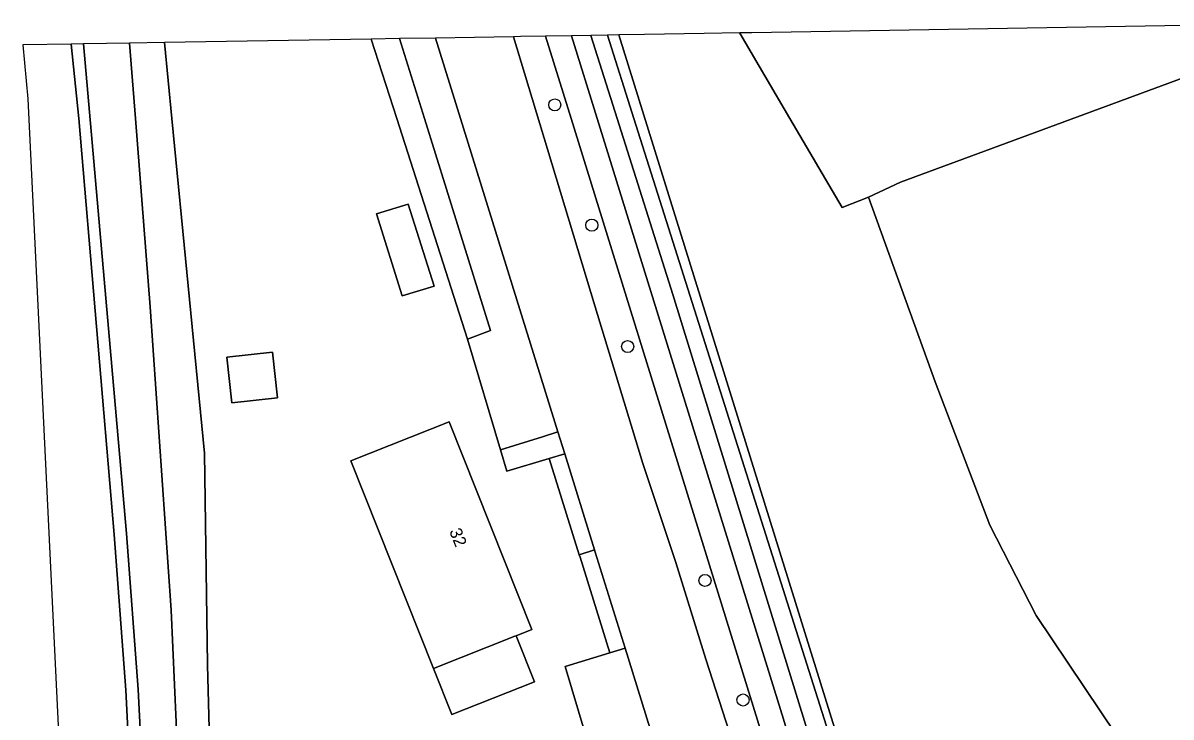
# Model space of a CAD drawing. Extents: x 162510 to 163918, y 388494 to 389774.
# Drawn here: x 162581.4 to 162674.3, y 389701.6 to 389757.7 of the extents above; entities that cross this region are included whole.
import ezdxf

# ---------------------------------------------------------------- set-up
doc = ezdxf.new("R2010")
doc.units = 0
for name, color, linetype in [('IMGEO_Berm_groen', 7, 'Continuous'), ('IMGEO_Boom', 7, 'Continuous'), ('IMGEO_Erf', 7, 'Continuous'), ('IMGEO_Fietspad_gesloten', 7, 'Continuous'), ('IMGEO_Grasland_agrarisch', 7, 'Continuous'), ('IMGEO_Groenvoorziening', 7, 'Continuous'), ('IMGEO_Pand', 7, 'Continuous'), ('IMGEO_Pand_nummerreeks', 7, 'Continuous'), ('IMGEO_Rijbaan_lokaal_gesloten', 7, 'Continuous'), ('IMGEO_Rijbaan_lokaal_open', 7, 'Continuous'), ('IMGEO_Rijbaan_regionaal_gesloten', 7, 'Continuous'), ('IMGEO_Voetpad_halfverhard', 7, 'Continuous'), ('IMGEO_Waterloop', 7, 'Continuous')]:
    doc.layers.add(name, color=color, linetype=linetype)

msp = doc.modelspace()

# ---------------------------------------------------------------- linework, layer by layer
at = {"layer": 'IMGEO_Berm_groen'}
for points in [[(162657.306, 389644.486), (162657.276, 389644.598), (162654.694, 389654.432), (162647.267, 389680.414), (162625.711, 389750), (162623.648, 389756.662), (162621.623, 389756.628), (162621.069, 389756.619)], [(162621.069, 389756.619), (162623.811, 389747.513), (162627.663, 389734.752), (162631.516, 389722.082), (162634.181, 389714.087), (162636.629, 389706.24), (162641.701, 389690.442), (162643.356, 389684.664)]]:
    msp.add_lwpolyline(points, dxfattribs=at)
at = {"layer": 'IMGEO_Boom'}
for centre in [(162624.392, 389751.1), (162627.393, 389741.373), (162630.292, 389731.545), (162636.548, 389712.625), (162639.625, 389702.949)]:
    msp.add_circle(centre, 0.489, dxfattribs=at)
at = {"layer": 'IMGEO_Erf'}
for points in [[(162687.277, 389757.733), (162683.292, 389757.666), (162640.344, 389756.943), (162639.372, 389756.927), (162639.379, 389756.914), (162643.424, 389750), (162647.635, 389742.802), (162649.788, 389743.642), (162652.361, 389744.846)], [(162609.981, 389742.277), (162612.545, 389743.081), (162614.626, 389736.448), (162612.061, 389735.643)], [(162598.275, 389726.987), (162597.869, 389730.701), (162601.554, 389731.103), (162601.959, 389727.389)], [(162607.907, 389722.307), (162615.852, 389725.465), (162622.536, 389708.654), (162621.265, 389708.149), (162622.743, 389704.431), (162616.069, 389701.778), (162614.591, 389705.496)]]:
    msp.add_lwpolyline(points, close=True, dxfattribs=at)
for points in [[(162627.859, 389696.902), (162625.249, 389705.649), (162628.847, 389706.767), (162626.436, 389714.516), (162626.377, 389714.707), (162623.952, 389722.498), (162620.528, 389721.472), (162620.012, 389723.199), (162617.339, 389732.159), (162611.612, 389750), (162609.55, 389756.425), (162592.82, 389756.143)], [(162592.82, 389756.143), (162593.42, 389750), (162596.065, 389722.909), (162596.294, 389705.791), (162596.643, 389692.431)]]:
    msp.add_lwpolyline(points, dxfattribs=at)
at = {"layer": 'IMGEO_Fietspad_gesloten'}
for points in [[(162656.158, 389656.625), (162642.905, 389701.409), (162627.834, 389750), (162625.756, 389756.697), (162623.648, 389756.662)], [(162623.648, 389756.662), (162625.711, 389750), (162647.267, 389680.414), (162654.694, 389654.432), (162657.276, 389644.598), (162657.306, 389644.486)]]:
    msp.add_lwpolyline(points, dxfattribs=at)
at = {"layer": 'IMGEO_Grasland_agrarisch'}
msp.add_lwpolyline([(162687.277, 389757.733), (162652.361, 389744.846), (162649.788, 389743.642), (162655.173, 389728.688), (162659.589, 389717.108), (162663.344, 389709.783), (162669.846, 389700.093), (162669.917, 389688.356), (162669.136, 389680.314), (162662.579, 389669.049), (162659.003, 389663.387), (162661.443, 389654.652), (162662.113, 389651.634), (162671.119, 389653.063), (162672.749, 389645.659), (162683.399, 389647.166)], dxfattribs=at)
at = {"layer": 'IMGEO_Groenvoorziening'}
for points in [[(162586.279, 389756.033), (162589.745, 389716.421), (162590.687, 389703.802), (162592.43, 389669.135), (162593.333, 389669.135), (162594.132, 389669.168), (162596.561, 389669.268), (162593.826, 389680.304), (162595.429, 389686.12), (162593.056, 389690.825), (162594.171, 389692.08), (162593.36, 389710.21), (162591.667, 389734.757), (162590.465, 389750), (162589.984, 389756.095)], [(162611.844, 389756.463), (162613.856, 389750), (162619.198, 389732.84), (162617.339, 389732.159), (162620.012, 389723.199), (162623.405, 389724.253), (162624.646, 389724.639), (162616.763, 389750), (162614.746, 389756.512)], [(162629.565, 389756.763), (162653.602, 389679.561), (162657.534, 389667.881), (162658.415, 389665.263), (162658.792, 389664.143), (162659.003, 389663.387), (162662.579, 389669.049), (162669.136, 389680.314), (162669.917, 389688.356), (162669.846, 389700.093), (162663.344, 389709.783), (162659.589, 389717.108), (162655.173, 389728.688), (162649.788, 389743.642), (162647.635, 389742.802), (162643.424, 389750), (162639.379, 389756.914), (162639.372, 389756.927), (162636.47, 389756.878), (162631.645, 389756.797)], [(162585.277, 389756.016), (162585.894, 389750), (162588.748, 389716.34), (162589.689, 389703.74), (162591.556, 389666.599), (162592.218, 389646.716), (162592.389, 389636.944), (162595.134, 389637.214), (162594.772, 389645.635), (162593.95, 389654.473), (162593.333, 389669.135), (162592.43, 389669.135), (162590.687, 389703.802), (162589.745, 389716.421), (162586.279, 389756.033)], [(162625.196, 389722.87), (162623.952, 389722.498), (162626.377, 389714.707), (162627.614, 389715.092)]]:
    msp.add_lwpolyline(points, close=True, dxfattribs=at)
for points in [[(162654.908, 389668.091), (162648.424, 389688.196), (162644.71, 389700.887), (162633.95, 389735.77), (162629.441, 389750), (162627.311, 389756.724), (162625.756, 389756.697), (162627.834, 389750), (162642.905, 389701.409), (162656.158, 389656.625)], [(162629.565, 389756.763), (162628.661, 389756.746), (162630.798, 389750), (162646.883, 389699.203), (162649.01, 389691.856), (162656.336, 389668.425)], [(162662.745, 389645.853), (162663.364, 389645.997), (162662.113, 389651.634), (162661.443, 389654.652), (162659.003, 389663.387), (162658.792, 389664.143), (162658.415, 389665.263), (162657.534, 389667.881), (162653.602, 389679.561), (162629.565, 389756.763)]]:
    msp.add_lwpolyline(points, dxfattribs=at)
at = {"layer": 'IMGEO_Pand'}
for points in [[(162612.545, 389743.081), (162609.981, 389742.277), (162612.061, 389735.643), (162614.626, 389736.448)], [(162597.869, 389730.701), (162598.275, 389726.987), (162601.959, 389727.389), (162601.554, 389731.103)], [(162615.852, 389725.465), (162607.907, 389722.307), (162614.591, 389705.496), (162621.152, 389708.104), (162621.265, 389708.149), (162622.536, 389708.654)], [(162621.265, 389708.149), (162621.152, 389708.104), (162614.591, 389705.496), (162616.069, 389701.778), (162622.743, 389704.431)]]:
    msp.add_lwpolyline(points, close=True, dxfattribs=at)
at = {"layer": 'IMGEO_Rijbaan_lokaal_gesloten'}
for points in [[(162643.356, 389684.664), (162641.701, 389690.442), (162636.629, 389706.24), (162634.181, 389714.087), (162631.516, 389722.082), (162627.663, 389734.752), (162623.811, 389747.513), (162621.069, 389756.619), (162614.746, 389756.512)], [(162614.746, 389756.512), (162616.763, 389750), (162624.646, 389724.639), (162625.196, 389722.87), (162627.614, 389715.092), (162627.673, 389714.901), (162630.082, 389707.151), (162632.791, 389698.435), (162634.173, 389693.988)]]:
    msp.add_lwpolyline(points, dxfattribs=at)
at = {"layer": 'IMGEO_Rijbaan_lokaal_open'}
msp.add_lwpolyline([(162627.614, 389715.092), (162626.377, 389714.707), (162626.436, 389714.516), (162628.847, 389706.767), (162630.082, 389707.151), (162627.673, 389714.901)], close=True, dxfattribs=at)
msp.add_lwpolyline([(162632.791, 389698.435), (162630.082, 389707.151), (162628.847, 389706.767), (162625.249, 389705.649), (162627.859, 389696.902), (162630.982, 389686.434), (162635.223, 389687.803), (162636.154, 389688.104)], dxfattribs=at)
at = {"layer": 'IMGEO_Rijbaan_regionaal_gesloten'}
msp.add_lwpolyline([(162591.255, 389539.455), (162592.3, 389571.45), (162592.615, 389589.606), (162592.643, 389612.42), (162592.648, 389616.266), (162592.627, 389622.514), (162593.018, 389622.497), (162592.85, 389626.934), (162592.621, 389626.918), (162592.437, 389634.206), (162592.389, 389636.944), (162592.218, 389646.716), (162591.556, 389666.599), (162589.689, 389703.74), (162588.748, 389716.34), (162585.894, 389750), (162585.277, 389756.016), (162581.37, 389755.95), (162581.764, 389751.603), (162588.947, 389603.291), (162582.931, 389467.226)], dxfattribs=at)
at = {"layer": 'IMGEO_Voetpad_halfverhard'}
msp.add_lwpolyline([(162624.646, 389724.639), (162623.405, 389724.253), (162620.012, 389723.199), (162620.528, 389721.472), (162623.952, 389722.498), (162625.196, 389722.87)], close=True, dxfattribs=at)
at = {"layer": 'IMGEO_Waterloop'}
for points in [[(162589.984, 389756.095), (162590.465, 389750), (162591.667, 389734.757), (162593.36, 389710.21), (162594.171, 389692.08), (162596.457, 389692.347), (162596.643, 389692.431), (162596.294, 389705.791), (162596.065, 389722.909), (162593.42, 389750), (162592.82, 389756.143)], [(162609.55, 389756.425), (162611.612, 389750), (162617.339, 389732.159), (162619.198, 389732.84), (162613.856, 389750), (162611.844, 389756.463)]]:
    msp.add_lwpolyline(points, close=True, dxfattribs=at)
for points in [[(162656.336, 389668.425), (162649.01, 389691.856), (162646.883, 389699.203), (162630.798, 389750), (162628.661, 389756.746), (162627.311, 389756.724)], [(162627.311, 389756.724), (162629.441, 389750), (162633.95, 389735.77), (162644.71, 389700.887), (162648.424, 389688.196), (162654.908, 389668.091)]]:
    msp.add_lwpolyline(points, dxfattribs=at)

# ---------------------------------------------------------------- texts
at = {"layer": 'IMGEO_Pand_nummerreeks'}
msp.add_text('32', height=1, rotation=291.68051, dxfattribs=at).set_placement((162615.84, 389716.619))

doc.saveas('drawing.dxf')
